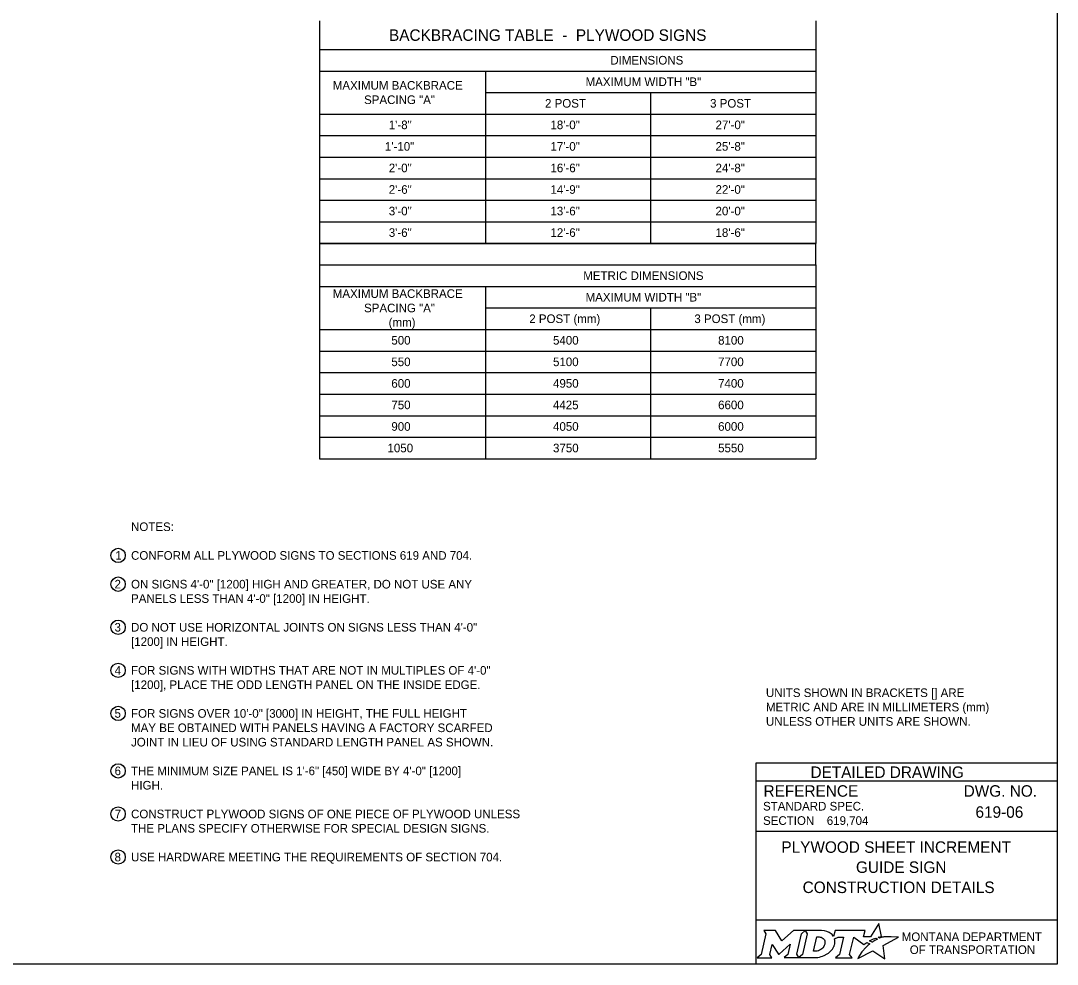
# Model space of a CAD drawing. Extents: x 49991.4 to 50021, y 49987.6 to 50011.4.
# Drawn here: x 50009.53 to 50016.75, y 49987.8 to 49994.37 of the extents above; entities that cross this region are included whole.
import ezdxf

# ---------------------------------------------------------------- set-up
doc = ezdxf.new("R2010")
doc.units = 0
for name, color, linetype in [('Default', 7, 'Continuous'), ('Level 1', 7, 'Continuous'), ('Level 2', 7, 'Continuous'), ('Level 5', 7, 'Continuous')]:
    doc.layers.add(name, color=color, linetype=linetype)

msp = doc.modelspace()

# ---------------------------------------------------------------- linework, layer by layer
at = {"layer": 'Default'}
for points in [[(50015.5126, 49987.9811), (50015.5023, 49987.9867), (50015.5139, 49987.9895), (50015.5255, 49987.9915), (50015.5081, 49988.0816), (50015.4486, 49987.9903), (50015.4013, 49987.9896), (50015.4116, 49988.0337), (50015.2024, 49988.0338), (50015.1923, 49987.9913), (50015.1865, 49987.9996)], [(50014.7056, 49988.0338), (50014.7197, 49988.0104), (50014.6862, 49987.8671), (50014.6605, 49987.8446), (50014.7621, 49987.8446), (50014.7486, 49987.8674), (50014.7648, 49987.9375), (50014.8085, 49987.8685), (50014.8138, 49987.8685), (50014.8889, 49987.938), (50014.8725, 49987.8669), (50014.8478, 49987.8449), (50014.9494, 49987.8449), (50014.9356, 49987.8682), (50014.9688, 49988.0106)], [(50014.9688, 49988.0106), (50014.9941, 49988.0338), (50014.9117, 49988.0338), (50014.8321, 49987.9608), (50014.7876, 49988.0335), (50014.7056, 49988.0338)], [(50015.1077, 49988.0338), (50014.9941, 49988.0338), (50015.0088, 49988.0109), (50014.9749, 49987.8671), (50014.9494, 49987.8449), (50015.06, 49987.8449)], [(50015.1317, 49987.9471), (50015.1305, 49987.939), (50015.1273, 49987.9297), (50015.1231, 49987.9215), (50015.1175, 49987.914), (50015.111, 49987.9071), (50015.1031, 49987.9008), (50015.0948, 49987.8961), (50015.0857, 49987.8922), (50015.0766, 49987.8899), (50015.0674, 49987.889), (50015.0515, 49987.889), (50015.0751, 49987.989), (50015.0911, 49987.989), (50015.0987, 49987.9884), (50015.1063, 49987.9865), (50015.1129, 49987.9835), (50015.119, 49987.9793), (50015.1238, 49987.9743), (50015.1275, 49987.9683), (50015.1302, 49987.9621), (50015.1318, 49987.9547), (50015.1318, 49987.9517), (50015.1317, 49987.9471)], [(50015.1991, 49987.9747), (50015.2237, 49987.9878), (50015.2606, 49987.9878), (50015.232, 49987.8673), (50015.2045, 49987.8446), (50015.3207, 49987.8446), (50015.3037, 49987.8675), (50015.3319, 49987.9877), (50015.4032, 49987.936), (50015.4243, 49987.9511), (50015.444, 49987.9402)], [(50015.3882, 49987.8843), (50015.3729, 49987.8599), (50015.3682, 49987.8524), (50015.3624, 49987.8438), (50015.3601, 49987.8395), (50015.4654, 49987.8926), (50015.5493, 49987.8375), (50015.5362, 49987.9302), (50015.6431, 49987.9886), (50015.5938, 49987.9894), (50015.5637, 49987.9898), (50015.5429, 49987.9901), (50015.5361, 49987.9886), (50015.5312, 49987.9874), (50015.5228, 49987.9851), (50015.5126, 49987.9811)], [(50015.4622, 49987.9535), (50015.4598, 49987.9518), (50015.4415, 49987.9614), (50015.4518, 49987.9671), (50015.4559, 49987.9693), (50015.4645, 49987.9733), (50015.4702, 49987.9759), (50015.4781, 49987.9789), (50015.4854, 49987.9816), (50015.4972, 49987.9742), (50015.4932, 49987.9721), (50015.4886, 49987.9696), (50015.4844, 49987.9674), (50015.4794, 49987.9645), (50015.4775, 49987.9634), (50015.4748, 49987.9618), (50015.4723, 49987.9604), (50015.47, 49987.9588), (50015.4674, 49987.957), (50015.4647, 49987.9552), (50015.4622, 49987.9535)], [(50015.1057, 49987.8522), (50015.1141, 49987.8548), (50015.1271, 49987.8602), (50015.1475, 49987.8712)], [(50015.4021, 49987.9004), (50015.4021, 49987.9004)]]:
    msp.add_lwpolyline(points, dxfattribs=at)
for centre, radius, start, end in [((50015.1308, 49987.9554), 0.0709, 339.53292, 15.85821), ((50015.0868, 49987.9727), 0.1183, 300.91025, 339.13831)]:
    msp.add_arc(centre, radius, start, end, dxfattribs=at)
for centre, major_axis, ratio, start_param, end_param in [((50015.1056, 49987.9864), (0.0834, -0.0037), 0.568097, 0.61298, 1.570796), ((50015.1612, 49987.9937), (0.0361, -0.0295), 0.469099, 1.225588, 1.570796), ((50015.4329, 49987.9305), (-0.0112, -0.0097), 0.021651, 3.157348, 6.283185), ((50015.3952, 49987.8923), (-0.00694, -0.00806), 0.008222, 0, 3.137361), ((50015.4119, 49987.9106), (-0.0098, -0.0102), 0.016458, 3.141593, 6.279097), ((50015.0603, 49987.9932), (0, 0.1484), 0.987302, 3.139398, 3.456847)]:
    msp.add_ellipse(centre, major_axis=major_axis, ratio=ratio, start_param=start_param, end_param=end_param, dxfattribs=at)
at = {"layer": 'Level 1'}
msp.add_lwpolyline([(49999.3835, 49998.9992), (50016.7501, 49998.9992), (50016.7501, 49987.7988), (49999.3835, 49987.7988)], close=True, dxfattribs=at)
at = {"layer": 'Level 2'}
for p, q in [((50011.6109, 49994.3685), (50011.6109, 49992.8185)), ((50015.0674, 49994.3685), (50015.0674, 49992.8185)), ((50011.6109, 49994.1685), (50015.0674, 49994.1685)), ((50011.6109, 49994.0185), (50015.0674, 49994.0185)), ((50012.7674, 49994.0185), (50012.7674, 49992.8185)), ((50012.7674, 49993.8685), (50015.0674, 49993.8685)), ((50013.9174, 49993.8685), (50013.9174, 49992.8185)), ((50011.6109, 49993.7185), (50015.0674, 49993.7185)), ((50011.6109, 49993.5685), (50015.0674, 49993.5685)), ((50011.6109, 49993.4185), (50015.0674, 49993.4185)), ((50011.6109, 49993.2685), (50015.0674, 49993.2685)), ((50011.6109, 49993.1185), (50015.0674, 49993.1185)), ((50011.6109, 49992.9685), (50015.0674, 49992.9685)), ((50011.6109, 49992.8185), (50015.0674, 49992.8185)), ((50015.0674, 49992.8185), (50011.6109, 49992.8185)), ((50011.6109, 49992.8185), (50011.6109, 49992.6685)), ((50011.6109, 49992.6685), (50011.6109, 49991.3185)), ((50015.0674, 49992.6685), (50015.0674, 49991.3185)), ((50011.6109, 49992.5185), (50015.0674, 49992.5185)), ((50012.7674, 49992.5185), (50012.7674, 49991.3185)), ((50012.7674, 49992.3685), (50015.0674, 49992.3685)), ((50013.9174, 49992.3685), (50013.9174, 49991.3185)), ((50011.6109, 49992.2185), (50015.0674, 49992.2185)), ((50011.6109, 49992.0685), (50015.0674, 49992.0685)), ((50011.6109, 49991.9185), (50015.0674, 49991.9185)), ((50011.6109, 49991.7685), (50015.0674, 49991.7685)), ((50011.6109, 49991.6185), (50015.0674, 49991.6185)), ((50011.6109, 49991.4685), (50015.0674, 49991.4685)), ((50011.6109, 49991.3185), (50015.0674, 49991.3185))]:
    msp.add_line(p, q, dxfattribs=at)
msp.add_lwpolyline([(50011.6109, 49992.6685), (50015.0674, 49992.6685), (50015.0674, 49992.8185)], dxfattribs=at)
for centre in [(50010.2077, 49990.6453), (50010.2077, 49990.4453), (50010.2077, 49990.1453), (50010.2077, 49989.8453), (50010.2077, 49989.5453), (50010.2077, 49989.1453), (50010.2077, 49988.8453), (50010.2077, 49988.5453)]:
    msp.add_circle(centre, 0.05, dxfattribs=at)
at = {"layer": 'Level 5'}
for p, q in [((50016.7501, 49989.1988), (50014.6501, 49989.1988)), ((50014.6501, 49989.1988), (50014.6501, 49987.7988)), ((50016.7501, 49989.0738), (50014.6501, 49989.0738)), ((50015.1444, 49988.7993), (50015.1444, 49988.7993)), ((50016.3862, 49988.8587), (50016.3862, 49988.8587)), ((50016.7501, 49988.7238), (50014.6501, 49988.7238)), ((50015.7001, 49988.4747), (50015.7001, 49988.4747)), ((50016.7501, 49988.1057), (50014.6501, 49988.1057))]:
    msp.add_line(p, q, dxfattribs=at)

# ---------------------------------------------------------------- texts
at = {"layer": 'Default'}
for s, p in [('MONTANA DEPARTMENT', (50015.6663, 49987.96)), ('OF TRANSPORTATION', (50015.7225, 49987.87))]:
    msp.add_text(s, height=0.06, dxfattribs=at).set_placement(p)
at = {"layer": 'Level 2'}
for s, height, p in [('BACKBRACING TABLE  -  PLYWOOD SIGNS', 0.08, (50012.0947, 49994.2285)), ('DIMENSIONS', 0.06, (50013.6367, 49994.0635)), ('MAXIMUM BACKBRACE', 0.06, (50011.7031, 49993.8885)), ('MAXIMUM WIDTH "B"', 0.06, (50013.4641, 49993.9135)), ('SPACING "A"', 0.06, (50011.921, 49993.7885)), ('2 POST', 0.06, (50013.1814, 49993.7635)), ('3 POST', 0.06, (50014.3314, 49993.7635)), ('1\'-8"', 0.06, (50012.0931, 49993.6135)), ('18\'-0"', 0.06, (50013.2194, 49993.6135)), ('27\'-0"', 0.06, (50014.3694, 49993.6135)), ('1\'-10"', 0.06, (50012.0662, 49993.4635)), ('17\'-0"', 0.06, (50013.2194, 49993.4635)), ('25\'-8"', 0.06, (50014.3694, 49993.4635)), ('2\'-0"', 0.06, (50012.0931, 49993.3135)), ('16\'-6"', 0.06, (50013.2194, 49993.3135)), ('24\'-8"', 0.06, (50014.3694, 49993.3135)), ('2\'-6"', 0.06, (50012.0931, 49993.1635)), ('14\'-9"', 0.06, (50013.2194, 49993.1635)), ('22\'-0"', 0.06, (50014.3694, 49993.1635)), ('3\'-0"', 0.06, (50012.0931, 49993.0135)), ('13\'-6"', 0.06, (50013.2194, 49993.0135)), ('20\'-0"', 0.06, (50014.3694, 49993.0135)), ('3\'-6"', 0.06, (50012.0931, 49992.8635)), ('12\'-6"', 0.06, (50013.2194, 49992.8635)), ('18\'-6"', 0.06, (50014.3694, 49992.8635)), ('METRIC DIMENSIONS', 0.06, (50013.4477, 49992.5635)), ('MAXIMUM BACKBRACE', 0.06, (50011.7031, 49992.4385)), ('MAXIMUM WIDTH "B"', 0.06, (50013.4641, 49992.4135)), ('SPACING "A"', 0.06, (50011.921, 49992.3385)), ('(mm)', 0.06, (50012.0922, 49992.2385)), ('2 POST (mm)', 0.06, (50013.0718, 49992.2635)), ('3 POST (mm)', 0.06, (50014.2218, 49992.2635)), ('500', 0.06, (50012.111, 49992.1135)), ('5400', 0.06, (50013.2373, 49992.1135)), ('8100', 0.06, (50014.3873, 49992.1135)), ('550', 0.06, (50012.111, 49991.9635)), ('5100', 0.06, (50013.2373, 49991.9635)), ('7700', 0.06, (50014.3873, 49991.9635)), ('600', 0.06, (50012.111, 49991.8135)), ('4950', 0.06, (50013.2373, 49991.8135)), ('7400', 0.06, (50014.3873, 49991.8135)), ('750', 0.06, (50012.111, 49991.6635)), ('4425', 0.06, (50013.2367, 49991.6635)), ('6600', 0.06, (50014.3873, 49991.6635)), ('900', 0.06, (50012.111, 49991.5135)), ('4050', 0.06, (50013.2373, 49991.5135)), ('6000', 0.06, (50014.3873, 49991.5135)), ('1050', 0.06, (50012.0841, 49991.3635)), ('3750', 0.06, (50013.2373, 49991.3635)), ('5550', 0.06, (50014.3873, 49991.3635)), ('NOTES:', 0.06, (50010.2977, 49990.8153)), ('CONFORM ALL PLYWOOD SIGNS TO SECTIONS 619 AND 704.', 0.06, (50010.2977, 49990.6153)), ('1', 0.06, (50010.1879, 49990.6153)), ('2', 0.06, (50010.1825, 49990.4153)), ('ON SIGNS 4\'-0" [1200] HIGH AND GREATER, DO NOT USE ANY ', 0.06, (50010.2977, 49990.4153)), ('PANELS LESS THAN 4\'-0" [1200] IN HEIGHT.', 0.06, (50010.2977, 49990.3153)), ('3', 0.06, (50010.1825, 49990.1153)), ('DO NOT USE HORIZONTAL JOINTS ON SIGNS LESS THAN 4\'-0" ', 0.06, (50010.2977, 49990.1153)), ('[1200] IN HEIGHT.', 0.06, (50010.2977, 49990.0153)), ('4', 0.06, (50010.1837, 49989.8153)), ('FOR SIGNS WITH WIDTHS THAT ARE NOT IN MULTIPLES OF 4\'-0" ', 0.06, (50010.2977, 49989.8153)), ('[1200], PLACE THE ODD LENGTH PANEL ON THE INSIDE EDGE.', 0.06, (50010.2977, 49989.7153)), ('UNITS SHOWN IN BRACKETS [] ARE ', 0.06, (50014.7206, 49989.6595)), ('METRIC AND ARE IN MILLIMETERS (mm) ', 0.06, (50014.7206, 49989.5595)), ('5', 0.06, (50010.1828, 49989.5153)), ('FOR SIGNS OVER 10\'-0" [3000] IN HEIGHT, THE FULL HEIGHT ', 0.06, (50010.2977, 49989.5153)), ('UNLESS OTHER UNITS ARE SHOWN.', 0.06, (50014.7206, 49989.4595)), ('MAY BE OBTAINED WITH PANELS HAVING A FACTORY SCARFED ', 0.06, (50010.2977, 49989.4153)), ('JOINT IN LIEU OF USING STANDARD LENGTH PANEL AS SHOWN.', 0.06, (50010.2977, 49989.3153)), ('6', 0.06, (50010.1832, 49989.1153)), ('THE MINIMUM SIZE PANEL IS 1\'-6" [450] WIDE BY 4\'-0" [1200] ', 0.06, (50010.2977, 49989.1153)), ('HIGH.', 0.06, (50010.2977, 49989.0153)), ('7', 0.06, (50010.1839, 49988.8153)), ('CONSTRUCT PLYWOOD SIGNS OF ONE PIECE OF PLYWOOD UNLESS', 0.06, (50010.2977, 49988.8153)), ('619-06', 0.08, (50016.1804, 49988.8187)), ('619,704', 0.06, (50015.1444, 49988.7693)), ('THE PLANS SPECIFY OTHERWISE FOR SPECIAL DESIGN SIGNS.', 0.06, (50010.2977, 49988.7153)), ('PLYWOOD SHEET INCREMENT', 0.08, (50014.8283, 49988.5747)), ('8', 0.06, (50010.1827, 49988.5153)), ('USE HARDWARE MEETING THE REQUIREMENTS OF SECTION 704.', 0.06, (50010.2977, 49988.5153)), ('GUIDE SIGN', 0.08, (50015.3478, 49988.4347)), ('CONSTRUCTION DETAILS', 0.08, (50014.9762, 49988.2947))]:
    msp.add_text(s, height=height, dxfattribs=at).set_placement(p)
at = {"layer": 'Level 5'}
for s, height, p in [('DETAILED DRAWING', 0.0799, (50015.0311, 49989.0963)), ('REFERENCE', 0.08, (50014.7037, 49988.9654)), ('DWG. NO.', 0.08, (50016.0979, 49988.9654)), ('STANDARD SPEC.', 0.06, (50014.7004, 49988.8694)), ('SECTION', 0.06, (50014.7004, 49988.7694))]:
    msp.add_text(s, height=height, dxfattribs=at).set_placement(p)

doc.saveas('drawing.dxf')
